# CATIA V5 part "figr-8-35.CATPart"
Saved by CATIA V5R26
Part number: Part1
Bounding box of the stored display mesh (mm): x -75 to 75, y -75 to 75, z 0 to 20
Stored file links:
  D:\_Deepak\CATIA\CATIA V5-6R2016_Deepak\Resources\Part files\Partfiles\c08_catia_v5_6r2016_prt\figr-8-35.CATPart
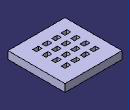
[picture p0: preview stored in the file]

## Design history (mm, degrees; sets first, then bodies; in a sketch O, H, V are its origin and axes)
Body1 (main body)
  Sketch1 on xy-plane, origin (0, 0, 0), H (1, 0, 0), V (0, 1, 0)
    line L1 (-75, 75) -> (75, 75)
    line L2 (75, 75) -> (75, -75)
    line L3 (75, -75) -> (-75, -75)
    line L4 (-75, -75) -> (-75, 75)
    axis line L5 (75, -75) -> (-75, 75)
    length L3 = 150
    length L2 = 150
    horizontal: L1 H, L3 H
    vertical: L2 V, L4 V
    midpoint: O L5
  Pad1: profile Sketch1, direction (0, 0, 1), length 20
  Sketch2 on face of Pad1, origin (0, 0, 20), H (1, 0, 0), V (0, 1, 0)
    line L1 (25, 40) -> (40, 40)
    line L2 (40, 40) -> (40, 30)
    line L3 (40, 30) -> (25, 30)
    line L4 (25, 30) -> (25, 40)
    reference projected line E1 (75, -75) -> (75, 75) from edge [face of Pad1 | face of Pad1]
    reference projected line E2 (75, 75) -> (-75, 75) from edge [face of Pad1 | face of Pad1]
    length L3 = 15
    length L4 = 10
    distance L2 E1 = 35
    distance L1 E2 = 35
    horizontal: L1 H, L3 H
    vertical: L2 V, L4 V
  Pocket1: profile Sketch2, direction (0, 0, -1), through (limit type 3)
  RectPattern1: of Pocket1, direction 1 instances 4, spacing -25, along end face of Pad1, direction 2 instances 4, spacing 25, along end face of Pad1 reversed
